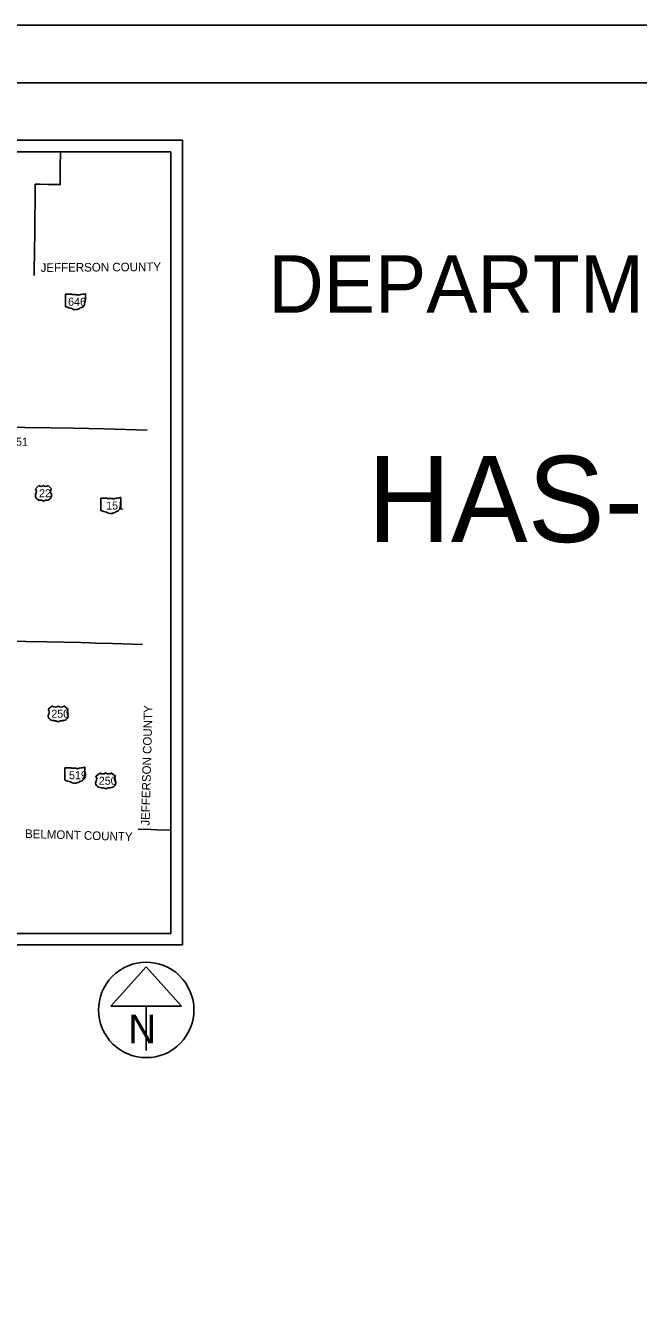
# Model space of a CAD drawing. Extents: x 0 to 34, y -32.5 to 22.
# Drawn here: x 7.63 to 12.97, y 10.98 to 22 of the extents above; entities that cross this region are included whole.
import ezdxf

# ---------------------------------------------------------------- set-up
doc = ezdxf.new("R2010")
doc.units = 0
for name, color, linetype in [('GM_X_Adjacent_County', 7, 'Continuous'), ('GM_X_County', 7, 'Continuous'), ('GM_X_County_Road_Text', 7, 'Continuous'), ('GM_X_County_ROW', 7, 'Continuous'), ('GM_X_Minor_Lake_Text', 7, 'Continuous'), ('GM_X_Minor_River', 7, 'Continuous'), ('GM_X_Minor_River_Text', 7, 'Continuous'), ('GM_X_Section', 7, 'Continuous'), ('GM_X_Township', 7, 'Continuous')]:
    doc.layers.add(name, color=color, linetype=linetype)

msp = doc.modelspace()

# ---------------------------------------------------------------- linework, layer by layer
at = {"layer": 'GM_X_County'}
msp.add_lwpolyline([(1.5, 21.5), (33.5, 21.5), (33.5, 0.5), (1.5, 0.5)], close=True, dxfattribs=at)
at = {"layer": 'GM_X_County_Road_Text'}
for points in [[(7.709, 19.823), (7.709, 19.861), (7.709, 19.873), (7.71, 19.899), (7.711, 20.001), (7.714, 20.239), (7.715, 20.35), (7.717, 20.442), (7.719, 20.618), (7.746, 20.617), (7.763, 20.617), (7.831, 20.616), (7.936, 20.614), (7.937, 20.631), (7.937, 20.644), (7.937, 20.688), (7.937, 20.723), (7.937, 20.736), (7.937, 20.767), (7.939, 20.9)], [(8.615, 15.007), (8.727, 15.004), (8.78, 15.003), (8.9, 14.999)]]:
    msp.add_lwpolyline(points, dxfattribs=at)
at = {"layer": 'GM_X_County_ROW'}
for points in [[(7.321, 16.646), (7.325, 16.786), (7.329, 17.003), (7.331, 17.165), (7.338, 17.444), (7.347, 17.445), (7.347, 17.498), (7.349, 17.608), (7.349, 17.642), (7.352, 17.833), (7.353, 17.89), (7.354, 17.962), (7.357, 18.15), (7.359, 18.296), (7.359, 18.331), (7.362, 18.506), (7.38, 18.506), (7.627, 18.503), (7.852, 18.498), (8.053, 18.495), (8.318, 18.489), (8.694, 18.478)], [(7.289, 15.044), (7.303, 15.476), (7.304, 15.544), (7.305, 15.577), (7.308, 15.577), (7.308, 15.723), (7.309, 15.847), (7.3, 15.847), (7.31, 16.112), (7.314, 16.268), (7.319, 16.517), (7.321, 16.642), (7.321, 16.646), (7.453, 16.644), (7.82, 16.637), (8.117, 16.63), (8.196, 16.627), (8.244, 16.626), (8.392, 16.623), (8.653, 16.613)]]:
    msp.add_lwpolyline(points, dxfattribs=at)
at = {"layer": 'GM_X_Minor_Lake_Text'}
for p, q in [((7.75, 17.997), (7.721, 17.968)), ((7.86, 17.968), (7.831, 17.997)), ((7.761, 17.869), (7.767, 17.869)), ((7.814, 17.869), (7.819, 17.869)), ((7.868, 16.079), (7.831, 16.05)), ((8.005, 16.05), (7.969, 16.079)), ((7.882, 15.951), (7.889, 15.951)), ((7.947, 15.951), (7.955, 15.951)), ((8.281, 15.496), (8.245, 15.467)), ((8.419, 15.467), (8.383, 15.496)), ((8.295, 15.368), (8.303, 15.368)), ((8.361, 15.368), (8.368, 15.368))]:
    msp.add_line(p, q, dxfattribs=at)
for centre, radius, start, end in [((7.688, 17.944), 0.0406, 334.5471, 35.0009), ((7.77, 18.017), 0.029, 225.573, 314.427), ((7.811, 18.017), 0.029, 225.573, 314.427), ((7.893, 17.944), 0.0406, 144.9991, 205.4529), ((7.761, 17.91), 0.0406, 154.8319, 270.6383), ((7.767, 17.84), 0.029, 36.8699, 90), ((7.814, 17.84), 0.029, 90, 143.1301), ((7.82, 17.91), 0.0406, 269.3617, 25.1681)]:
    msp.add_arc(centre, radius, start, end, dxfattribs=at)
for centre, major_axis, start_param, end_param in [((7.882, 15.992), (0.0508, 0), 2.702327, 4.723529), ((7.79, 16.026), (0.0508, 0), 5.838949, 6.894067), ((7.893, 16.099), (-0.0363, 0), 0.795399, 2.346194), ((7.944, 16.099), (-0.0363, 0), 0.795399, 2.346194), ((7.955, 15.992), (-0.0508, 0), 1.559657, 3.580859), ((8.047, 16.026), (-0.0508, 0), 5.672304, 6.727422), ((7.889, 15.922), (-0.0363, 0), 3.785094, 4.712389), ((7.947, 15.922), (-0.0363, 0), 4.712389, 5.639684), ((8.295, 15.409), (0.0508, 0), 2.702327, 4.723529), ((8.203, 15.444), (0.0508, 0), 5.838949, 6.894067), ((8.306, 15.517), (-0.0363, 0), 0.795399, 2.346194), ((8.357, 15.517), (-0.0363, 0), 0.795399, 2.346194), ((8.369, 15.409), (-0.0508, 0), 1.559657, 3.580859), ((8.46, 15.444), (-0.0508, 0), 5.672304, 6.727422), ((8.303, 15.339), (-0.0363, 0), 3.785094, 4.712389), ((8.361, 15.339), (-0.0363, 0), 4.712389, 5.639684)]:
    msp.add_ellipse(centre, major_axis=major_axis, ratio=0.8, start_param=start_param, end_param=end_param, dxfattribs=at)
at = {"layer": 'GM_X_Minor_River_Text'}
for p, q in [((7.981, 19.66), (7.981, 19.554)), ((8.034, 19.661), (7.983, 19.661)), ((8.155, 19.609), (8.155, 19.664)), ((8.155, 19.609), (8.155, 19.609)), ((8.289, 17.886), (8.289, 17.78)), ((8.342, 17.888), (8.291, 17.888)), ((8.463, 17.835), (8.463, 17.891)), ((8.463, 17.835), (8.463, 17.835)), ((7.976, 15.54), (7.976, 15.434)), ((8.029, 15.542), (7.978, 15.542)), ((8.15, 15.489), (8.15, 15.544)), ((8.15, 15.489), (8.15, 15.489))]:
    msp.add_line(p, q, dxfattribs=at)
for centre, major_axis, start_param, end_param in [((7.983, 19.66), (0.00202, 0), 1.712693, 3.28349), ((8.046, 19.674), (0.0196, 0), 4.042523, 4.731795), ((8.052, 19.602), (0.0702, 0), 1.404758, 1.657858), ((8.068, 19.66), (0.00564, 0), 3.836095, 5.185415), ((8.077, 19.648), (0.0117, 0), 0.950623, 2.079405), ((8.092, 19.665), (0.0141, 0), 4.081561, 5.145723), ((8.117, 19.629), (0.0371, 0), 1.699011, 2.107814), ((8.093, 19.805), (0.185, 0), 4.814394, 5.042369), ((8.153, 19.664), (0.00194, 0), 6.141152, 7.989035), ((8.153, 19.608), (0.00207, 0), 5.05454, 6.418171), ((7.983, 19.554), (0.00203, 0), 3.00124, 4.508301), ((7.983, 19.564), (0.0155, 0), 4.665946, 4.897461), ((7.987, 19.548), (0.0056, 0), 0.519207, 1.627899), ((8.057, 19.643), (0.133, 0), 4.195997, 4.488961), ((8.017, 19.506), (0.0417, 0), 0.823519, 1.323587), ((8.063, 19.547), (0.0265, 0), 4.026481, 4.996735), ((8.078, 19.511), (0.0217, 0), 1.495662, 1.94098), ((8.08, 19.539), (0.0141, 0), 4.691044, 5.507374), ((8.093, 19.529), (0.00397, 0), 1.147584, 2.315152), ((8.091, 19.544), (0.0149, 0), 4.937069, 5.64225), ((8.123, 19.524), (0.0253, 0), 1.647645, 2.488434), ((8.103, 19.579), (0.0462, 0), 5.101752, 6.440018), ((8.162, 19.586), (0.0131, 0), 2.387724, 3.262537), ((8.155, 19.605), (0.003, 0), 1.883978, 3.671073), ((8.136, 19.598), (0.018, 0), 5.934695, 6.695948), ((8.291, 17.886), (0.00202, 0), 1.712693, 3.28349), ((8.354, 17.9), (0.0196, 0), 4.042523, 4.731795), ((8.36, 17.829), (0.0702, 0), 1.404758, 1.657858), ((8.376, 17.887), (0.00564, 0), 3.836095, 5.185415), ((8.385, 17.875), (0.0117, 0), 0.950623, 2.079405), ((8.4, 17.891), (0.0141, 0), 4.081561, 5.145723), ((8.425, 17.856), (0.0371, 0), 1.699011, 2.107814), ((8.401, 18.032), (0.185, 0), 4.814394, 5.042369), ((8.461, 17.891), (0.00194, 0), 6.141152, 7.989035), ((8.291, 17.78), (0.00203, 0), 3.00124, 4.508301), ((8.291, 17.791), (0.0155, 0), 4.665946, 4.897461), ((8.295, 17.774), (0.0056, 0), 0.519207, 1.627899), ((8.365, 17.869), (0.133, 0), 4.195997, 4.488961), ((8.325, 17.733), (0.0417, 0), 0.823519, 1.323587), ((8.371, 17.774), (0.0265, 0), 4.026481, 4.996735), ((8.386, 17.737), (0.0217, 0), 1.495662, 1.94098), ((8.388, 17.766), (0.0141, 0), 4.691044, 5.507374), ((8.401, 17.756), (0.00397, 0), 1.147584, 2.315152), ((8.399, 17.77), (0.0149, 0), 4.937069, 5.64225), ((8.431, 17.751), (0.0253, 0), 1.647645, 2.488434), ((8.411, 17.805), (0.0462, 0), 5.101752, 6.440018), ((8.47, 17.812), (0.0131, 0), 2.387724, 3.262537), ((8.463, 17.831), (0.003, 0), 1.883978, 3.671073), ((8.444, 17.824), (0.018, 0), 5.934695, 6.695948), ((8.461, 17.835), (0.00207, 0), 5.05454, 6.418171), ((7.978, 15.54), (0.00202, 0), 1.712693, 3.28349), ((8.041, 15.554), (0.0196, 0), 4.042523, 4.731795), ((8.048, 15.483), (0.0702, 0), 1.404758, 1.657858), ((8.063, 15.541), (0.00564, 0), 3.836095, 5.185415), ((8.072, 15.529), (0.0117, 0), 0.950623, 2.079405), ((8.087, 15.545), (0.0141, 0), 4.081561, 5.145723), ((8.112, 15.51), (0.0371, 0), 1.699011, 2.107814), ((8.088, 15.686), (0.185, 0), 4.814394, 5.042369), ((8.148, 15.545), (0.00194, 0), 6.141152, 7.989035), ((7.978, 15.434), (0.00203, 0), 3.00124, 4.508301), ((7.979, 15.445), (0.0155, 0), 4.665946, 4.897461), ((7.982, 15.428), (0.0056, 0), 0.519207, 1.627899), ((8.052, 15.523), (0.133, 0), 4.195997, 4.488961), ((8.118, 15.405), (0.0253, 0), 1.647645, 2.488434), ((8.099, 15.459), (0.0462, 0), 5.101752, 6.440018), ((8.157, 15.466), (0.0131, 0), 2.387724, 3.262537), ((8.15, 15.485), (0.003, 0), 1.883978, 3.671073), ((8.131, 15.478), (0.018, 0), 5.934695, 6.695948), ((8.148, 15.489), (0.00207, 0), 5.05454, 6.418171), ((8.013, 15.387), (0.0417, 0), 0.823519, 1.323587), ((8.058, 15.428), (0.0265, 0), 4.026481, 4.996735), ((8.073, 15.391), (0.0217, 0), 1.495662, 1.94098), ((8.075, 15.42), (0.0141, 0), 4.691044, 5.507374), ((8.088, 15.41), (0.00397, 0), 1.147584, 2.315152), ((8.086, 15.424), (0.0149, 0), 4.937069, 5.64225)]:
    msp.add_ellipse(centre, major_axis=major_axis, ratio=0.8, start_param=start_param, end_param=end_param, dxfattribs=at)
at = {"layer": 'GM_X_Section'}
msp.add_lwpolyline([(0, 0), (34, 0), (34, 22), (0, 22)], close=True, dxfattribs=at)
at = {"layer": 'GM_X_Township'}
for p, q in [((2, 21), (9, 21)), ((9, 21), (9, 14)), ((2.1, 20.9), (8.9, 20.9)), ((8.9, 20.9), (8.9, 14.1)), ((2, 14), (9, 14)), ((2.1, 14.1), (8.9, 14.1)), ((8.685, 13.809), (8.377, 13.468)), ((8.992, 13.468), (8.685, 13.809)), ((8.377, 13.468), (8.992, 13.468)), ((8.685, 13.468), (8.685, 13.081)), ((8.685, 13.435), (8.685, 13.435)), ((8.685, 13.435), (8.685, 13.435))]:
    msp.add_line(p, q, dxfattribs=at)
msp.add_arc((8.685, 13.435), 0.415, 129.7798, 129.7633, dxfattribs=at)

# ---------------------------------------------------------------- texts
at = {"layer": 'GM_X_Adjacent_County'}
for s, height, p in [('DEPARTMENT OF TRANSPORTATION', 0.5, (9.747, 19.5)), ('HAS-9-VAR, HAS-646-1.15', 0.75, (10.612, 17.505))]:
    msp.add_text(s, height=height, dxfattribs=at).set_placement(p)
at = {"layer": 'GM_X_Minor_Lake_Text'}
for s, p in [('22', (7.752, 17.895)), ('250', (7.859, 15.977)), ('250', (8.272, 15.394))]:
    msp.add_text(s, height=0.0696, dxfattribs=at).set_placement(p)
at = {"layer": 'GM_X_Minor_River'}
for s, rotation, p in [('JEFFERSON COUNTY', 0.4072, (7.766, 19.855)), ('JEFFERSON COUNTY', 88.5722, (8.714, 15.037)), ('BELMONT COUNTY', 358.3527, (7.629, 14.931))]:
    msp.add_text(s, height=0.075, rotation=rotation, dxfattribs=at).set_placement(p)
at = {"layer": 'GM_X_Minor_River_Text'}
for s, p in [('646', (8.005, 19.561)), ('151', (7.5, 18.343)), ('151', (8.336, 17.788)), ('519', (8.013, 15.442))]:
    msp.add_text(s, height=0.0696, dxfattribs=at).set_placement(p)
at = {"layer": 'GM_X_Township'}
msp.add_text('N', height=0.25, dxfattribs=at).set_placement((8.529, 13.144))

doc.saveas('drawing.dxf')
